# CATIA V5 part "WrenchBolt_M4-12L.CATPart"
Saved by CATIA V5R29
Part number: WrenchBolt_M4-12L
Source: Unknown
Bounding box of the stored display mesh (mm): x -3.61 to 3.61, y -3.61 to 3.61, z -12 to 4
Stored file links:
  C:\가치같이\SmartFactory_BoxErectorConveyor\Boxing(under)\WrenchBolt_M4-12L.CATPart
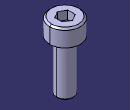
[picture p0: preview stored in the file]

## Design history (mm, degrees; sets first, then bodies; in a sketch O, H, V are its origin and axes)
Body1 (main body)
  Solid1 "PartBody": solid without history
